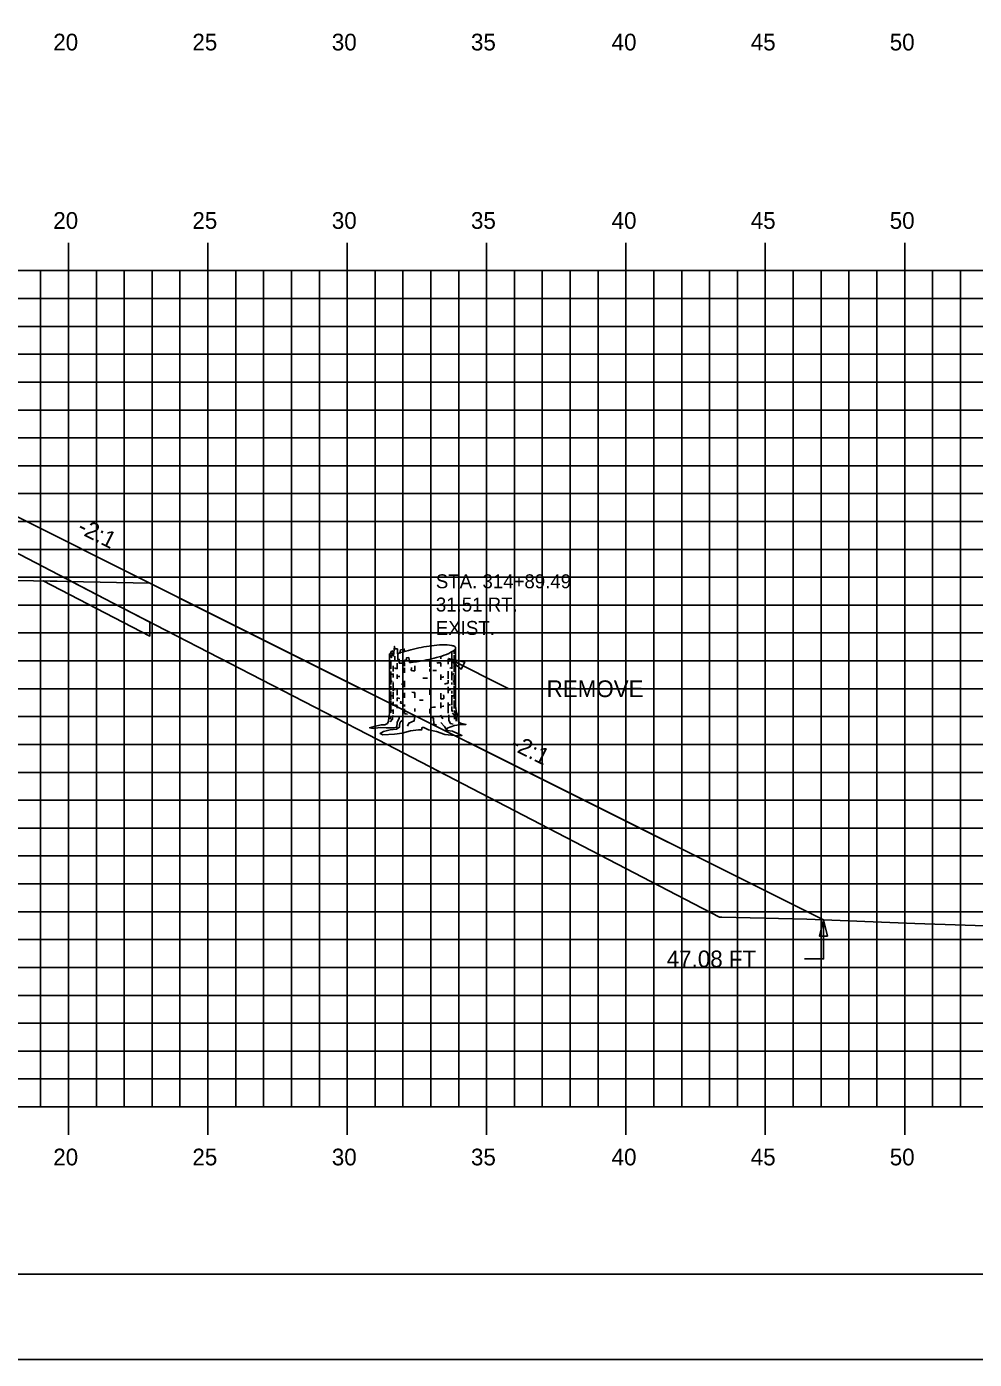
# Model space of a CAD drawing. Extents: x 1138541 to 1138711, y 608981 to 609091.
# Drawn here: x 1138642.94 to 1138676.94, y 608981.28 to 609029.09 of the extents above; entities that cross this region are included whole.
import ezdxf

# ---------------------------------------------------------------- set-up
doc = ezdxf.new("R2010")
doc.units = 0
for name, color, linetype in [('ANNOTATION', 7, 'Continuous'), ('BORDER', 7, 'Continuous'), ('D_Roadway_SlopeLines', 7, 'Continuous'), ('D_Roadway_SubGrade', 7, 'Continuous'), ('D_Text_Monospaced', 7, 'Continuous'), ('D_Text_Standard', 7, 'Continuous'), ('H_V ANNOTATION', 7, 'Continuous'), ('MAJOR', 7, 'Continuous'), ('MINOR', 7, 'Continuous'), ('PLOT BOUNDARY', 7, 'Continuous'), ('S_Roadway_Centerline', 7, 'Continuous'), ('S_Trees_Decid_Pay', 7, 'Continuous'), ('SHADING', 7, 'Continuous')]:
    doc.layers.add(name, color=color, linetype=linetype)

msp = doc.modelspace()

# ---------------------------------------------------------------- linework, layer by layer
msp.add_lwpolyline([(1138576.228, 608996.48), (1138599.518, 609008.124), (1138601.518, 609009.124), (1138606.435, 609011.583), (1138606.436, 609011.583), (1138613.436, 609011.863), (1138624.436, 609012.083), (1138635.436, 609011.863), (1138642.436, 609011.583), (1138647.352, 609009.124), (1138649.352, 609008.124), (1138671.518, 608997.041)])
at = {"layer": 'BORDER'}
msp.add_lwpolyline([(1138549.436, 608984.335), (1138709.436, 608984.335), (1138709.436, 609089.335), (1138549.436, 609089.335)], close=True, dxfattribs=at)
at = {"layer": 'D_Roadway_SlopeLines'}
for points in [[(1138645.964, 609009.819), (1138671.518, 608997.041)], [(1138647.352, 609007.726), (1138647.352, 609007.226), (1138643.525, 609009.201)], [(1138647.352, 609009.124), (1138649.352, 609008.124)], [(1138649.352, 609008.124), (1138671.518, 608997.041)]]:
    msp.add_lwpolyline(points, dxfattribs=at)
at = {"layer": 'D_Roadway_SubGrade'}
msp.add_lwpolyline([(1138635.436, 609011.446), (1138635.436, 609011.613), (1138642.436, 609011.333), (1138642.436, 609011.583), (1138642.436, 609011.583), (1138647.352, 609009.124), (1138635.436, 609009.363)], close=True, dxfattribs=at)
at = {"layer": 'D_Text_Standard'}
for points in [[(1138658.069, 609006.424), (1138660.23, 609005.335), (1138660.91, 609005.335)], [(1138671.518, 608997.041), (1138671.524, 608995.642), (1138670.844, 608995.642)]]:
    msp.add_lwpolyline(points, dxfattribs=at)
for points in [[(1138658.069, 609006.424), (1138658.654, 609006.292), (1138658.523, 609006.032)], [(1138671.518, 608997.041), (1138671.666, 608996.46), (1138671.375, 608996.459)]]:
    msp.add_lwpolyline(points, close=True, dxfattribs=at)
at = {"layer": 'MAJOR'}
for p, q in [((1138644.436, 609021.337), (1138644.436, 609020.335)), ((1138649.436, 609021.337), (1138649.436, 609020.335)), ((1138654.436, 609021.337), (1138654.436, 609020.335)), ((1138659.436, 609021.337), (1138659.436, 609020.335)), ((1138664.436, 609021.337), (1138664.436, 609020.335)), ((1138669.436, 609021.337), (1138669.436, 609020.335)), ((1138674.436, 609021.337), (1138674.436, 609020.335)), ((1138554.436, 609020.335), (1138694.436, 609020.335)), ((1138554.436, 609020.335), (1138694.436, 609020.335)), ((1138644.436, 608990.335), (1138644.436, 609020.335)), ((1138649.436, 608990.335), (1138649.436, 609020.335)), ((1138654.436, 608990.335), (1138654.436, 609020.335)), ((1138659.436, 608990.335), (1138659.436, 609020.335)), ((1138664.436, 608990.335), (1138664.436, 609020.335)), ((1138669.436, 608990.335), (1138669.436, 609020.335)), ((1138674.436, 608990.335), (1138674.436, 609020.335)), ((1138554.436, 609015.335), (1138694.436, 609015.335)), ((1138554.436, 609010.335), (1138694.436, 609010.335)), ((1138554.436, 609005.335), (1138694.436, 609005.335)), ((1138554.436, 609000.335), (1138694.436, 609000.335)), ((1138554.436, 608995.335), (1138694.436, 608995.335)), ((1138554.436, 608990.335), (1138694.436, 608990.335)), ((1138554.436, 608990.335), (1138694.436, 608990.335)), ((1138644.436, 608989.333), (1138644.436, 608990.335)), ((1138649.436, 608989.333), (1138649.436, 608990.335)), ((1138654.436, 608989.333), (1138654.436, 608990.335)), ((1138659.436, 608989.333), (1138659.436, 608990.335)), ((1138664.436, 608989.333), (1138664.436, 608990.335)), ((1138669.436, 608989.333), (1138669.436, 608990.335)), ((1138674.436, 608989.333), (1138674.436, 608990.335))]:
    msp.add_line(p, q, dxfattribs=at)
at = {"layer": 'MINOR'}
for p, q in [((1138643.436, 608990.335), (1138643.436, 609020.335)), ((1138645.436, 608990.335), (1138645.436, 609020.335)), ((1138646.436, 608990.335), (1138646.436, 609020.335)), ((1138647.436, 608990.335), (1138647.436, 609020.335)), ((1138648.436, 608990.335), (1138648.436, 609020.335)), ((1138650.436, 608990.335), (1138650.436, 609020.335)), ((1138651.436, 608990.335), (1138651.436, 609020.335)), ((1138652.436, 608990.335), (1138652.436, 609020.335)), ((1138653.436, 608990.335), (1138653.436, 609020.335)), ((1138655.436, 608990.335), (1138655.436, 609020.335)), ((1138656.436, 608990.335), (1138656.436, 609020.335)), ((1138657.436, 608990.335), (1138657.436, 609020.335)), ((1138658.436, 608990.335), (1138658.436, 609020.335)), ((1138660.436, 608990.335), (1138660.436, 609020.335)), ((1138661.436, 608990.335), (1138661.436, 609020.335)), ((1138662.436, 608990.335), (1138662.436, 609020.335)), ((1138663.436, 608990.335), (1138663.436, 609020.335)), ((1138665.436, 608990.335), (1138665.436, 609020.335)), ((1138666.436, 608990.335), (1138666.436, 609020.335)), ((1138667.436, 608990.335), (1138667.436, 609020.335)), ((1138668.436, 608990.335), (1138668.436, 609020.335)), ((1138670.436, 608990.335), (1138670.436, 609020.335)), ((1138671.436, 608990.335), (1138671.436, 609020.335)), ((1138672.436, 608990.335), (1138672.436, 609020.335)), ((1138673.436, 608990.335), (1138673.436, 609020.335)), ((1138675.436, 608990.335), (1138675.436, 609020.335)), ((1138676.436, 608990.335), (1138676.436, 609020.335)), ((1138554.436, 609019.335), (1138694.436, 609019.335)), ((1138554.436, 609018.335), (1138694.436, 609018.335)), ((1138554.436, 609017.335), (1138694.436, 609017.335)), ((1138554.436, 609016.335), (1138694.436, 609016.335)), ((1138554.436, 609014.335), (1138694.436, 609014.335)), ((1138554.436, 609013.335), (1138694.436, 609013.335)), ((1138554.436, 609012.335), (1138694.436, 609012.335)), ((1138554.436, 609011.335), (1138694.436, 609011.335)), ((1138554.436, 609009.335), (1138694.436, 609009.335)), ((1138554.436, 609008.335), (1138694.436, 609008.335)), ((1138554.436, 609007.335), (1138694.436, 609007.335)), ((1138554.436, 609006.335), (1138694.436, 609006.335)), ((1138554.436, 609004.335), (1138694.436, 609004.335)), ((1138554.436, 609003.335), (1138694.436, 609003.335)), ((1138554.436, 609002.335), (1138694.436, 609002.335)), ((1138554.436, 609001.335), (1138694.436, 609001.335)), ((1138554.436, 608999.335), (1138694.436, 608999.335)), ((1138554.436, 608998.335), (1138694.436, 608998.335)), ((1138554.436, 608997.335), (1138694.436, 608997.335)), ((1138554.436, 608996.335), (1138694.436, 608996.335)), ((1138554.436, 608994.335), (1138694.436, 608994.335)), ((1138554.436, 608993.335), (1138694.436, 608993.335)), ((1138554.436, 608992.335), (1138694.436, 608992.335)), ((1138554.436, 608991.335), (1138694.436, 608991.335))]:
    msp.add_line(p, q, dxfattribs=at)
at = {"layer": 'PLOT BOUNDARY'}
msp.add_lwpolyline([(1138541.342, 608981.276), (1138711.342, 608981.276), (1138711.342, 609091.276), (1138541.342, 609091.276)], close=True, dxfattribs=at)
at = {"layer": 'S_Roadway_Centerline'}
msp.add_lwpolyline([(1138638.229, 609012.472), (1138646.037, 609008.404), (1138655.547, 609003.497), (1138667.798, 608997.142), (1138667.879, 608997.141), (1138670.921, 608997.065), (1138674.795, 608996.915), (1138680.938, 608996.715), (1138685.408, 608996.58), (1138694.436, 608996.256)], dxfattribs=at)
at = {"layer": 'S_Trees_Decid_Pay'}
for p, q in [((1138656.149, 609006.505), (1138656.149, 609006.331)), ((1138657.789, 609006.498), (1138657.789, 609006.411)), ((1138658.194, 609006.664), (1138658.194, 609006.411)), ((1138658.274, 609006.709), (1138658.274, 609006.588)), ((1138658.274, 609006.536), (1138658.274, 609006.322)), ((1138655.999, 609006.305), (1138655.999, 609006.051)), ((1138656.085, 609006.16), (1138656.085, 609005.948)), ((1138656.234, 609006.257), (1138656.234, 609006.052)), ((1138656.495, 609006.259), (1138656.495, 609006.139)), ((1138656.495, 609006.087), (1138656.495, 609005.902)), ((1138656.733, 609005.987), (1138656.738, 609006.094)), ((1138656.86, 609006.16), (1138656.86, 609005.98)), ((1138657.406, 609006.396), (1138657.406, 609006.116)), ((1138657.406, 609006.051), (1138657.406, 609005.948)), ((1138657.789, 609006.27), (1138657.789, 609006.131)), ((1138658.061, 609006.411), (1138658.061, 609006.219)), ((1138658.194, 609006.314), (1138658.194, 609006.051)), ((1138658.274, 609006.277), (1138658.274, 609005.939)), ((1138655.999, 609005.954), (1138655.999, 609005.484)), ((1138656.085, 609005.882), (1138656.085, 609005.734)), ((1138656.085, 609005.557), (1138656.085, 609005.256)), ((1138656.234, 609005.845), (1138656.234, 609005.69)), ((1138656.495, 609005.616), (1138656.495, 609005.388)), ((1138657.789, 609005.845), (1138657.789, 609005.653)), ((1138658.061, 609005.968), (1138658.061, 609005.69)), ((1138658.061, 609005.645), (1138658.061, 609005.536)), ((1138658.194, 609005.954), (1138658.194, 609005.645)), ((1138658.194, 609005.557), (1138658.194, 609005.49)), ((1138658.274, 609005.822), (1138658.274, 609005.461)), ((1138655.999, 609005.433), (1138655.999, 609005.299)), ((1138655.999, 609005.242), (1138655.999, 609004.916)), ((1138656.085, 609005.219), (1138656.085, 609004.976)), ((1138656.234, 609005.328), (1138656.234, 609005.108)), ((1138656.495, 609005.19), (1138656.495, 609005.005)), ((1138656.86, 609005.202), (1138656.86, 609005.005)), ((1138657.406, 609005.336), (1138657.406, 609005.116)), ((1138657.789, 609005.173), (1138657.789, 609004.965)), ((1138658.061, 609005.402), (1138658.061, 609005.173)), ((1138658.194, 609005.256), (1138658.194, 609005.159)), ((1138658.194, 609005.108), (1138658.194, 609004.748)), ((1138658.274, 609005.425), (1138658.274, 609004.976)), ((1138655.999, 609004.887), (1138655.999, 609004.467)), ((1138656.085, 609004.865), (1138656.085, 609004.725)), ((1138656.085, 609004.593), (1138656.085, 609004.436)), ((1138656.234, 609005.008), (1138656.234, 609004.887)), ((1138656.234, 609004.736), (1138656.234, 609004.638)), ((1138656.495, 609004.77), (1138656.495, 609004.693)), ((1138656.495, 609004.616), (1138656.495, 609004.442)), ((1138656.86, 609004.622), (1138656.86, 609004.519)), ((1138657.406, 609004.616), (1138657.406, 609004.442)), ((1138657.789, 609004.844), (1138657.789, 609004.644)), ((1138658.061, 609004.844), (1138658.061, 609004.461)), ((1138658.194, 609004.696), (1138658.194, 609004.529)), ((1138658.274, 609004.91), (1138658.274, 609004.628)), ((1138656.003, 609004.364), (1138655.988, 609004.247)), ((1138657.784, 609004.387), (1138657.864, 609004.255))]:
    msp.add_line(p, q, dxfattribs=at)
for points in [[(1138655.949, 609006.58), (1138655.949, 609004.442), (1138655.929, 609004.301), (1138655.923, 609004.175), (1138655.879, 609004.088), (1138655.787, 609004.039), (1138655.651, 609004.039), (1138655.408, 609003.983), (1138655.241, 609003.934), (1138655.383, 609003.903), (1138655.62, 609003.94), (1138655.83, 609003.928), (1138656.091, 609003.934), (1138656.215, 609003.952), (1138656.245, 609003.91), (1138656.308, 609003.952), (1138656.209, 609003.885), (1138655.974, 609003.86), (1138655.743, 609003.798), (1138655.614, 609003.728), (1138655.713, 609003.685), (1138656.135, 609003.704), (1138656.413, 609003.747), (1138656.711, 609003.823), (1138656.997, 609003.86), (1138657.102, 609003.86), (1138657.121, 609003.94), (1138657.189, 609003.946), (1138657.356, 609003.86), (1138657.642, 609003.804), (1138657.94, 609003.697), (1138658.4, 609003.648), (1138658.554, 609003.66), (1138658.212, 609003.811), (1138658.009, 609003.841), (1138658.02, 609003.915), (1138658.28, 609004.015), (1138658.455, 609004.045), (1138658.696, 609004.057), (1138658.498, 609004.095), (1138658.436, 609004.131), (1138658.412, 609004.218), (1138658.4, 609004.387), (1138658.354, 609004.473), (1138658.326, 609004.714), (1138658.326, 609006.8)], [(1138656.305, 609006.252), (1138656.297, 609006.396), (1138656.252, 609006.389), (1138656.238, 609006.763), (1138656.143, 609006.771), (1138656.129, 609006.851), (1138656.091, 609006.514), (1138656.046, 609006.608), (1138656.026, 609006.454), (1138655.949, 609006.58), (1138655.955, 609006.39)], [(1138655.949, 609006.58), (1138655.995, 609006.602), (1138656.017, 609006.668), (1138656.069, 609006.691), (1138656.102, 609006.616)], [(1138656.327, 609006.618), (1138656.348, 609006.726), (1138656.48, 609006.757), (1138656.488, 609006.669)], [(1138656.467, 609006.257), (1138656.503, 609006.36), (1138656.569, 609006.366), (1138656.569, 609006.448), (1138656.643, 609006.454), (1138656.668, 609006.274)], [(1138657.902, 609004.979), (1138657.901, 609005.056), (1138657.893, 609005.122)], [(1138656.357, 609004.887), (1138656.348, 609004.813), (1138656.423, 609004.807), (1138656.437, 609004.924)], [(1138656.069, 609004.372), (1138656.062, 609004.247), (1138655.98, 609004.152)], [(1138656.215, 609003.952), (1138656.234, 609004.131), (1138656.295, 609004.268), (1138656.289, 609004.368)], [(1138656.406, 609004.2), (1138656.332, 609004.131), (1138656.314, 609004.033), (1138656.308, 609003.952)], [(1138656.858, 609004.335), (1138656.841, 609004.181), (1138656.643, 609004.101), (1138656.598, 609003.998)], [(1138657.423, 609004.327), (1138657.526, 609004.276), (1138657.541, 609004.07), (1138657.644, 609004.041)], [(1138658.009, 609003.841), (1138657.922, 609003.983), (1138657.79, 609004.125)], [(1138658.078, 609004.401), (1138658.078, 609004.196), (1138658.136, 609004.086), (1138658.233, 609004.07)], [(1138658.219, 609004.475), (1138658.29, 609004.372), (1138658.29, 609004.247)], [(1138658.276, 609004.556), (1138658.336, 609004.395), (1138658.35, 609004.27), (1138658.342, 609004.173)]]:
    msp.add_lwpolyline(points, dxfattribs=at)
for centre, radius, start, end in [((1138656.759, 609005.392), 1.299, 107.8613, 113.3069), ((1138658.239, 609000.799), 6.126, 100.7779, 107.8613), ((1138658.239, 609000.799), 6.126, 93.6944, 100.7779), ((1138656.037, 609012.367), 6.126, 280.7779, 287.8613), ((1138657.928, 609005.615), 1.299, 78.2779, 93.6944), ((1138657.517, 609007.773), 1.299, 287.8613, 303.2779), ((1138658.094, 609006.418), 0.48, 69.9843, 78.2779), ((1138657.967, 609007.088), 0.48, 303.2779, 311.5714), ((1138658.202, 609006.714), 0.164, 55.7779, 69.9843), ((1138658.176, 609006.852), 0.164, 311.5714, 325.7779), ((1138658.234, 609006.761), 0.107, 45.9547, 55.7779), ((1138658.264, 609006.792), 0.0645, 33.2779, 45.9547), ((1138658.223, 609006.82), 0.107, 325.7779, 335.6011), ((1138658.272, 609006.797), 0.0544, 22.46, 33.2779), ((1138658.262, 609006.802), 0.0645, 335.6011, 348.2779), ((1138658.28, 609006.8), 0.0467, 10.7779, 22.46), ((1138658.28, 609006.8), 0.0467, 359.0957, 10.7779), ((1138658.272, 609006.8), 0.0544, 348.2779, 359.0957), ((1138655.997, 609006.211), 0.0476, 180, 191.6815), ((1138656.004, 609006.213), 0.0554, 191.6815, 202.5), ((1138656.014, 609006.217), 0.0657, 202.5, 215.1737), ((1138656.049, 609006.242), 0.109, 215.1737, 225), ((1138656.09, 609006.282), 0.166, 225, 239.1924), ((1138656.562, 609007.302), 1.292, 250.6119, 255.2856), ((1138656.348, 609007.551), 1.299, 268.1289, 273.6944), ((1138656.037, 609012.367), 6.126, 273.6944, 274.0246), ((1138656.037, 609012.367), 6.126, 275.9147, 280.7779), ((1138657.139, 609012.15), 5.916, 274.9515, 276.3087), ((1138657.715, 609007.562), 1.292, 285.5651, 289.0916), ((1138657.714, 609007.302), 1.292, 288.0829, 292.5), ((1138658.023, 609006.555), 0.484, 297.4162, 300.8076), ((1138658.186, 609006.282), 0.166, 300.8076, 315), ((1138658.186, 609006.543), 0.166, 301.67, 315), ((1138658.226, 609006.242), 0.109, 315, 324.8263), ((1138658.227, 609006.503), 0.109, 315, 324.8263), ((1138658.262, 609006.217), 0.0657, 324.8263, 337.5), ((1138658.263, 609006.478), 0.0657, 324.8263, 337.5), ((1138658.271, 609006.213), 0.0554, 337.5, 348.3185), ((1138658.272, 609006.474), 0.0554, 337.5, 348.3185), ((1138655.997, 609005.69), 0.0476, 180, 191.6815), ((1138656.004, 609005.692), 0.0554, 191.6815, 202.5), ((1138656.014, 609005.696), 0.0657, 202.5, 215.1737), ((1138656.049, 609005.721), 0.109, 215.1737, 225), ((1138656.09, 609005.761), 0.166, 225, 239.1924), ((1138656.09, 609006.019), 0.166, 237.0378, 239.1924), ((1138656.253, 609006.292), 0.484, 239.1924, 247.5), ((1138656.253, 609006.034), 0.484, 239.1924, 245.7725), ((1138656.562, 609007.038), 1.292, 247.5, 248.3537), ((1138656.562, 609006.781), 1.292, 247.5, 248.4842), ((1138656.562, 609007.038), 1.292, 255.2856, 259.2632), ((1138657.138, 609011.889), 5.916, 266.0776, 267.3043), ((1138657.138, 609011.626), 5.916, 270.1162, 271.7708), ((1138657.138, 609011.889), 5.916, 273.5382, 274.8924), ((1138657.138, 609011.626), 5.916, 276.3184, 277.1546), ((1138657.714, 609007.038), 1.292, 277.1546, 278.3662), ((1138657.714, 609006.781), 1.292, 279.2565, 285.6105), ((1138657.714, 609007.038), 1.292, 291.8071, 292.5), ((1138658.023, 609006.292), 0.484, 292.5, 300.8076), ((1138658.023, 609006.034), 0.484, 294.6372, 300.8076), ((1138658.186, 609006.019), 0.166, 300.8076, 301.6001), ((1138658.186, 609005.761), 0.166, 300.8076, 315), ((1138658.226, 609005.721), 0.109, 315, 324.8263), ((1138658.262, 609005.696), 0.0657, 324.8263, 337.5), ((1138658.271, 609005.692), 0.0554, 337.5, 348.3185), ((1138655.997, 609005.433), 0.0476, 180, 191.6815), ((1138655.997, 609005.167), 0.0476, 180, 191.6815), ((1138656.004, 609005.434), 0.0554, 191.6815, 202.5), ((1138656.004, 609005.169), 0.0554, 191.6815, 202.5), ((1138656.014, 609005.438), 0.0657, 202.5, 215.1737), ((1138656.014, 609005.173), 0.0657, 202.5, 215.1737), ((1138656.049, 609005.463), 0.109, 215.1737, 225), ((1138656.049, 609005.198), 0.109, 215.1737, 225), ((1138656.09, 609005.504), 0.166, 225, 239.1924), ((1138656.09, 609005.238), 0.166, 225, 239.1924), ((1138656.253, 609005.511), 0.484, 239.1924, 247.5), ((1138656.562, 609006.523), 1.292, 247.5, 251.799), ((1138656.562, 609006.258), 1.292, 247.5, 248.3537), ((1138656.562, 609006.781), 1.292, 261.8726, 262.8454), ((1138657.138, 609011.369), 5.916, 262.8454, 263.7595), ((1138657.138, 609011.111), 5.916, 266.2721, 267.3043), ((1138657.714, 609006.523), 1.292, 285.6105, 290.1001), ((1138658.023, 609005.511), 0.484, 292.5, 300.8076), ((1138658.186, 609005.238), 0.166, 300.8076, 302.0694), ((1138658.186, 609005.504), 0.166, 302.0694, 315), ((1138658.226, 609005.463), 0.109, 315, 324.8263), ((1138658.262, 609005.438), 0.0657, 324.8263, 337.5), ((1138658.271, 609005.434), 0.0554, 337.5, 348.3185), ((1138658.271, 609005.169), 0.0554, 337.5, 348.3185), ((1138655.997, 609004.638), 0.0476, 180, 191.6815), ((1138656.004, 609004.64), 0.0554, 191.6815, 202.5), ((1138656.014, 609004.644), 0.0657, 202.5, 215.1737), ((1138656.049, 609004.669), 0.109, 215.1737, 225), ((1138656.09, 609004.709), 0.166, 225, 239.1924), ((1138656.253, 609004.982), 0.484, 239.1924, 247.5), ((1138656.253, 609005.24), 0.484, 242.734, 247.5), ((1138656.562, 609005.986), 1.292, 251.3664, 255.2856), ((1138656.562, 609006.258), 1.292, 255.2856, 259.2463), ((1138657.138, 609010.846), 5.916, 268.9207, 270), ((1138657.138, 609010.846), 5.916, 270, 270.2757), ((1138657.138, 609010.574), 5.916, 273.2637, 274.461), ((1138657.138, 609010.846), 5.916, 276.3184, 277.1546), ((1138657.138, 609010.574), 5.916, 276.3184, 277.1546), ((1138657.714, 609006.258), 1.292, 277.1546, 278.3795), ((1138657.714, 609005.986), 1.292, 277.1546, 278.3662), ((1138657.714, 609005.986), 1.292, 285.6105, 289.1534), ((1138658.186, 609004.967), 0.166, 302.0694, 315), ((1138658.226, 609004.926), 0.109, 315, 324.8263), ((1138658.262, 609004.901), 0.0657, 324.8263, 337.5), ((1138658.271, 609004.897), 0.0554, 337.5, 348.3185), ((1138656.562, 609005.728), 1.292, 247.5, 248.3537), ((1138657.138, 609010.316), 5.916, 263.7831, 264.7656), ((1138657.723, 609005.732), 1.292, 291.3696, 292.0604), ((1138658.023, 609004.982), 0.484, 292.5, 296.5499)]:
    msp.add_arc(centre, radius, start, end, dxfattribs=at)
at = {"layer": 'SHADING'}
msp.add_line((1138644.547, 609009.181), (1138643.525, 609009.201), dxfattribs=at)
for points in [[(1138643.525, 609009.201), (1138647.352, 609007.226), (1138647.352, 609007.726)], [(1138647.352, 609007.726), (1138646.037, 609008.404), (1138644.547, 609009.181)]]:
    msp.add_lwpolyline(points, dxfattribs=at)

# ---------------------------------------------------------------- texts
at = {"layer": 'ANNOTATION'}
for rotation, p in [(333.4354, (1138644.717, 609010.96)), (333.4349, (1138660.259, 609003.189))]:
    msp.add_text('-2:1', height=0.6, rotation=rotation, dxfattribs=at).set_placement(p)
at = {"layer": 'D_Text_Monospaced'}
for s, height, p in [('STA. 314+89.49', 0.49998, (1138657.616, 609008.94)), ('31.51 RT.', 0.5, (1138657.616, 609008.106)), ('EXIST. ', 0.5, (1138657.616, 609007.266))]:
    msp.add_text(s, height=height, dxfattribs=at).set_placement(p)
at = {"layer": 'D_Text_Standard'}
for s, p in [('REMOVE', (1138661.59, 609005.035)), ('47.08 FT', (1138665.899, 608995.342))]:
    msp.add_text(s, height=0.6, dxfattribs=at).set_placement(p)
at = {"layer": 'H_V ANNOTATION'}
for s, p in [('20', (1138643.89, 609028.235)), ('25', (1138648.882, 609028.235)), ('30', (1138653.884, 609028.235)), ('35', (1138658.876, 609028.235)), ('40', (1138663.922, 609028.235)), ('45', (1138668.914, 609028.235)), ('50', (1138673.9, 609028.235)), ('20', (1138643.89, 609021.835)), ('25', (1138648.882, 609021.835)), ('30', (1138653.884, 609021.835)), ('35', (1138658.876, 609021.835)), ('40', (1138663.922, 609021.835)), ('45', (1138668.914, 609021.835)), ('50', (1138673.9, 609021.835)), ('20', (1138643.89, 608988.235)), ('25', (1138648.882, 608988.235)), ('30', (1138653.884, 608988.235)), ('35', (1138658.876, 608988.235)), ('40', (1138663.922, 608988.235)), ('45', (1138668.914, 608988.235)), ('50', (1138673.9, 608988.235))]:
    msp.add_text(s, height=0.6, dxfattribs=at).set_placement(p)

doc.saveas('drawing.dxf')
